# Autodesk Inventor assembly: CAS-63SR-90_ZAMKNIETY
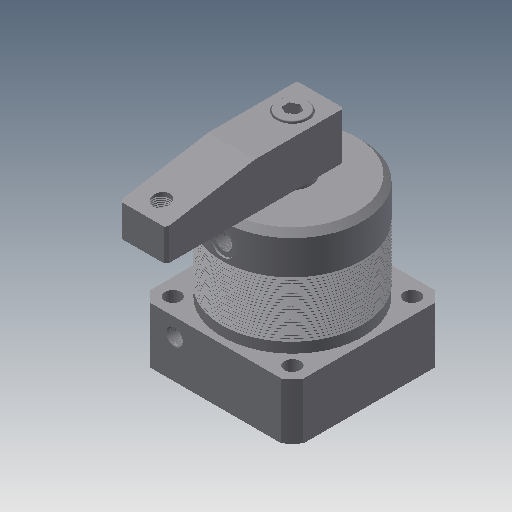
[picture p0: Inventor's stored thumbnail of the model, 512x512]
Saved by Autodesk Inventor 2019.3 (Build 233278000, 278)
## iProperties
Created: 2009-09
Part Number: CAS-63SR-90_ZAMKNIETY
Material: Ogólny
Document SubType Name: Assembly
Designer: CADENGINEERING4
Sending System: PRO/ENGINEER BY PARAMETRIC TECHNOLOGY CORPORATION, 2007170
Preprocessor: PRO/ENGINEER BY PARAMETRIC TECHNOLOGY CORPORATION, 2007170
Title: CAS-63S_ASM
Author: Administrator
Revision Number: 1LAST_VERSION
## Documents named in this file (7)
- D:\Vault_2016\Projekty\STRONA\Pneumatic\Line ; Pipe connecct - type\cas-63s_asm\CAS-63SR-90_ZAMKNIETY.iam
- D:\Vault_2016\Projekty\STRONA\Pneumatic\Line ; Pipe connecct - type\cas-63s_asm\CAS-63BT.ipt
- D:\Vault_2016\Projekty\STRONA\Pneumatic\Line ; Pipe connecct - type\cas-63s_asm\CAS-63SHSG.ipt
- D:\Vault_2016\Projekty\STRONA\Pneumatic\Line ; Pipe connecct - type\cas-63s_asm\CAS-63HG.ipt
- D:\Vault_2016\Projekty\STRONA\Pneumatic\Line ; Pipe connecct - type\cas-63s_asm\M4.ipt
- D:\Vault_2016\Projekty\STRONA\Pneumatic\Line ; Pipe connecct - type\cas-63s_asm\CAS-63SYB.ipt
- D:\Vault_2016\Projekty\STRONA\Pneumatic\Line ; Pipe connecct - type\cas-63s_asm\M10LC.ipt
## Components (11 placed, 11 different names)
1. CAS-63BT_0 — Zestawiające:5, Kątowe:1, Równoległe:1
2. CAS-63SHSG_1 — Zestawiające:1, Zestawiające:2, Zestawiające:4, Zestawiające:5
3. CAS-63HG_2
4. M4_3
5. M4_4
6. M4_5
7. M4_6
8. M4_7
9. M4_8
10. CAS-63SYB_9 — Zestawiające:1, Zestawiające:3, Zestawiające:4, Kątowe:1, Równoległe:1
11. M10LC_10 — Zestawiające:2, Zestawiające:3
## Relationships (7: Mate 5, Angle 1, Flush 1)
- Zestawiające:1 [Mate]: CAS-63SHSG_1 ↔ CAS-63SYB_9
- Zestawiające:2 [Mate]: CAS-63SHSG_1 ↔ M10LC_10
- Zestawiające:3 [Mate]: CAS-63SYB_9 ↔ M10LC_10
- Zestawiające:4 [Mate]: CAS-63SHSG_1 ↔ CAS-63SYB_9
- Zestawiające:5 [Mate]: CAS-63BT_0 ↔ CAS-63SHSG_1
- Kątowe:1 [Angle]: CAS-63BT_0 ↔ CAS-63SYB_9
- Równoległe:1 [Flush]: CAS-63BT_0 ↔ CAS-63SYB_9
